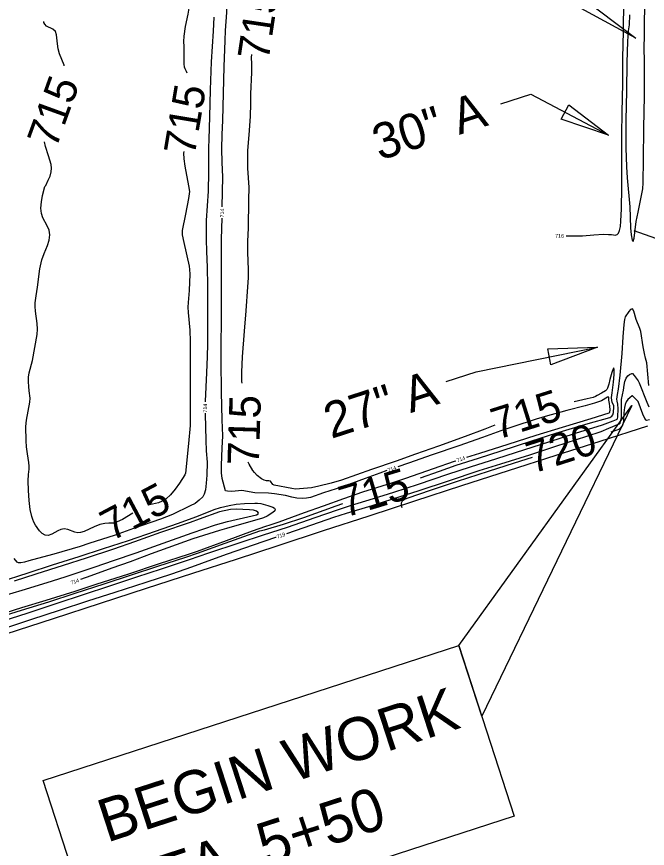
# Model space of a CAD drawing. Extents: x -468563856 to 36492962, y -306094093 to 11899197.
# Drawn here: x 1823721 to 1824382, y 531405 to 532278 of the extents above; entities that cross this region are included whole.
import ezdxf

# ---------------------------------------------------------------- set-up
doc = ezdxf.new("R2010")
doc.units = 0
for name, color, linetype in [('DT_X_Contour_Minor', 7, 'Continuous'), ('Level 14', 7, 'Continuous'), ('Level 19', 7, 'Continuous'), ('Level 40', 7, 'Continuous'), ('SH_Text', 7, 'Continuous')]:
    doc.layers.add(name, color=color, linetype=linetype)

msp = doc.modelspace()

# ---------------------------------------------------------------- linework, layer by layer
at = {"layer": 'DT_X_Contour_Minor'}
for points in [[(1823936.35, 532078.45), (1823936.84, 532109.8), (1823936.37, 532124.67), (1823935.82, 532139.18), (1823936.31, 532154.27), (1823936.92, 532168.73), (1823937.48, 532197.51), (1823938.25, 532225.05), (1823939.35, 532252.79), (1823939.74, 532263.35), (1823941.09, 532282.1), (1823941.07, 532286.43), (1823940.19, 532299.37), (1823939.03, 532314.28), (1823939, 532322.4), (1823939.58, 532333.47), (1823939.57, 532335.1)], [(1823900.62, 532322.38), (1823902.49, 532304.97), (1823902.74, 532297.16), (1823901.79, 532288.98), (1823900.27, 532280.33), (1823897.5, 532267.5), (1823895.93, 532257.35), (1823895.65, 532251.73), (1823895.98, 532246.56), (1823896.09, 532228.14), (1823896.49, 532225.16), (1823897.07, 532223.46), (1823898.5, 532220.8), (1823899.3, 532218.83)], [(1824296.77, 532047.81), (1824313.98, 532048.01), (1824326.04, 532048.84), (1824335.94, 532049.65), (1824341.47, 532049.4), (1824344.46, 532049.14), (1824346.56, 532049.13), (1824348.3, 532048.76), (1824349.31, 532048.82), (1824350.53, 532049.37), (1824351.81, 532050.79), (1824352.95, 532053.49), (1824353.8, 532057.73), (1824354.37, 532063.21), (1824354.99, 532076.15), (1824355.22, 532098.93), (1824355.27, 532129.3), (1824355.26, 532153.68), (1824355.59, 532177.75), (1824356.27, 532207.58), (1824356.51, 532234.37), (1824356.94, 532262.76), (1824357.52, 532294.42)], [(1824363.4, 532279.71), (1824362.83, 532269.19), (1824361.89, 532263.08), (1824361.18, 532251.83), (1824360.5, 532229.71), (1824360.19, 532200.16), (1824359.61, 532168.94), (1824359.6, 532140.1), (1824360.05, 532120.3), (1824360.82, 532108.7), (1824363.65, 532078.16), (1824364.37, 532056.36), (1824365.13, 532048.96), (1824366.14, 532043.44), (1824367.17, 532041.8), (1824368.08, 532045.41), (1824370.43, 532062.77), (1824372.28, 532072.86), (1824377.4, 532097.37), (1824377.78, 532103.67), (1824378.03, 532128.04), (1824378.24, 532160.96), (1824379.06, 532194.65), (1824379.18, 532218.7), (1824379.03, 532236.19), (1824378.85, 532239.97), (1824378.92, 532263.33), (1824379.43, 532296.21)], [(1823770.76, 532226.24), (1823770.62, 532226.78), (1823765.81, 532238.79), (1823764.36, 532244.05), (1823763.43, 532249.41), (1823762.66, 532258.77), (1823761.34, 532262.23), (1823758.6, 532264.66), (1823752.13, 532268), (1823750.26, 532269.76), (1823749.37, 532271.53), (1823749.13, 532272.88)], [(1823927.36, 532277.28), (1823926.67, 532262.57), (1823924.85, 532230.5), (1823923.7, 532201.14), (1823922.98, 532172.63), (1823922.35, 532149.37), (1823921.91, 532140.19), (1823921.98, 532114.75), (1823921.47, 532094.64), (1823919.63, 532063.92), (1823919.36, 532044.19), (1823919.96, 532031.4), (1823920.68, 532015.11), (1823920.99, 531995.3), (1823920.79, 531965.16), (1823920.76, 531934.35), (1823920.61, 531921.2), (1823919.81, 531904.04), (1823918.41, 531874.62), (1823918.41, 531873.76)], [(1823957.11, 531893.22), (1823956.91, 531895.16), (1823956.87, 531904.8), (1823957.7, 531921.1), (1823959.64, 531947.83), (1823961.58, 531969.23), (1823963.12, 531994.35), (1823964.02, 532003.83), (1823963.93, 532012.68), (1823963.01, 532030.56), (1823963.1, 532042.41), (1823963.83, 532056.08), (1823964.31, 532085.69), (1823964.48, 532098.76), (1823963.31, 532118.91), (1823963.27, 532137.51), (1823963.7, 532145.5), (1823965.03, 532158.44), (1823965.95, 532173.45), (1823966.26, 532186.26), (1823966.37, 532196.82), (1823967.43, 532219.13), (1823967.22, 532228.32), (1823967.09, 532235.12), (1823967.26, 532237.99)], [(1823842.53, 531757.04), (1823831.85, 531750.48), (1823823.12, 531746.45), (1823817.59, 531746.52), (1823813.21, 531746.14), (1823807.94, 531744.96), (1823802.18, 531742.75), (1823791.61, 531737.86), (1823787.88, 531736.64), (1823784.84, 531736.47), (1823781.79, 531737.18), (1823774.31, 531739.89), (1823770.54, 531740.56), (1823767.2, 531740), (1823764.1, 531738.53), (1823757.52, 531734.85), (1823753.98, 531733.72), (1823750.57, 531733.83), (1823747.51, 531735.52), (1823744.83, 531738.32), (1823740.57, 531744.52), (1823738.96, 531747.41), (1823737.65, 531750.34), (1823736.63, 531753.48), (1823735.11, 531760.86), (1823733.94, 531770.17), (1823733.12, 531780.89), (1823732.86, 531790.82), (1823733.31, 531797.51), (1823733.78, 531803.14), (1823733.78, 531806.39), (1823733.51, 531810.2), (1823732.2, 531819.21), (1823731.06, 531826.43), (1823730.63, 531832.89), (1823730.5, 531847.78), (1823731.02, 531854.6), (1823734.67, 531873.36), (1823734.86, 531877.59), (1823734.04, 531885.24), (1823733.47, 531889.72), (1823733.12, 531894.61), (1823733.26, 531899.54), (1823734.04, 531904.23), (1823737.36, 531917.04), (1823742.38, 531944.37), (1823742.74, 531950.08), (1823742.16, 531955.9), (1823740.42, 531969.05), (1823740.13, 531973.64), (1823740.27, 531977.53), (1823741.4, 531984.94), (1823742.76, 531994.12), (1823745, 532013.22), (1823747.25, 532022.89), (1823749.45, 532029.42), (1823752.97, 532037.79), (1823754.77, 532043.33), (1823755.56, 532048.86), (1823754.75, 532053.81), (1823752.8, 532058.25), (1823748.26, 532066.7), (1823746.72, 532071.4), (1823746.14, 532076.99), (1823746.67, 532083.61), (1823747.86, 532090.21), (1823750.17, 532099.52), (1823751.23, 532100.72), (1823753.96, 532106.21), (1823755.74, 532110.63), (1823757.06, 532115.08), (1823757.45, 532118.93), (1823756.98, 532122.58), (1823754.2, 532131.75), (1823751.01, 532141.73), (1823749.93, 532146.48)], [(1823895.95, 532136.49), (1823895.71, 532134.58), (1823895.99, 532128.66), (1823897.07, 532120.83), (1823900.94, 532100.27), (1823901.95, 532094.45), (1823901.79, 532091.89), (1823901.07, 532087.11), (1823897.87, 532070.58), (1823894.36, 532053.67), (1823894.15, 532051.26), (1823894.34, 532048.91), (1823896.04, 532040.98), (1823901.68, 532016.18), (1823902.12, 532012.64), (1823902.18, 532007.61), (1823901.55, 531990.54), (1823900.7, 531977.85), (1823900.09, 531973.08), (1823900.49, 531967.48), (1823902.27, 531948.94), (1823902.8, 531937.11), (1823902.77, 531918.95), (1823902.6, 531885.94), (1823902.63, 531853.43), (1823902.57, 531848.94), (1823900.83, 531829.95), (1823897.89, 531799.03), (1823897.02, 531797.32), (1823891.43, 531788.56), (1823886.89, 531782.2), (1823882.11, 531776.33), (1823877.67, 531772.11), (1823873.5, 531769.43), (1823869.33, 531767.86), (1823860.15, 531765.9), (1823858.51, 531765.34)], [(1824109.08, 531801.63), (1824101.49, 531799), (1824086.27, 531793.49), (1824062.27, 531784.52), (1824042.53, 531778.19), (1824028.73, 531773.58), (1824024.55, 531772.57), (1824020.45, 531772.43), (1824014.43, 531772.68), (1824009.23, 531773.79), (1824002.52, 531775.37), (1823991.15, 531777.26), (1823984.89, 531777.81), (1823970.52, 531778.46), (1823956.86, 531780.65), (1823946.38, 531779.76), (1823941.95, 531780.12), (1823939.65, 531780.58), (1823936.39, 531793.47), (1823935.82, 531796.36), (1823935.54, 531799.1), (1823935.58, 531807.46), (1823936.38, 531825.25), (1823936.9, 531838.23), (1823936.24, 531855.03), (1823935.45, 531883.75), (1823935.04, 531916.68), (1823935.14, 531933.74), (1823935.55, 531958.58), (1823935.65, 531991.41), (1823935.42, 532021.22), (1823935.62, 532044.42), (1823936.1, 532066.45)], [(1824383.57, 531891), (1824381.43, 531914.77), (1824380.29, 531919.45), (1824378.92, 531924.51), (1824377.62, 531931.53), (1824375.16, 531947.4), (1824374.25, 531950.68), (1824370.41, 531960.26), (1824367.85, 531968.95), (1824366.33, 531971.29), (1824364.51, 531970.77), (1824362.6, 531968.47), (1824358.74, 531963.02), (1824358.01, 531960.14), (1824357.34, 531954.92), (1824356.32, 531942.06), (1824355.24, 531924.38), (1824353.11, 531901.79), (1824351.55, 531887.2), (1824350.55, 531881.53), (1824349.61, 531876.44), (1824350.02, 531874.52), (1824350.72, 531871.47), (1824351, 531866.36), (1824350.75, 531858.08), (1824350.31, 531856.01), (1824349.91, 531855.34), (1824349.28, 531854.83), (1824346.04, 531853.47), (1824334.56, 531849.28), (1824306.53, 531840.69), (1824278.26, 531831.62), (1824253.23, 531823.42), (1824224.03, 531814.11), (1824196.14, 531805.42), (1824172.51, 531797.63), (1824141.77, 531787.05), (1824116.03, 531778.69), (1824094.41, 531772.1)], [(1824144.21, 531793.99), (1824164.06, 531801.15), (1824181.65, 531807.42), (1824205.01, 531814.8), (1824228.79, 531822.36), (1824260.88, 531832.71), (1824286.24, 531840.79), (1824319.87, 531851.19), (1824342.61, 531857.47), (1824344.86, 531858.63), (1824345.99, 531860.24), (1824346.6, 531862.6), (1824347.06, 531868.64), (1824346.91, 531869.67), (1824345.25, 531873.3), (1824344.71, 531875.11), (1824344.5, 531878.46), (1824345.24, 531883.28), (1824346.72, 531894.54), (1824347.28, 531902.47), (1824347.41, 531907.08), (1824347.06, 531909.49), (1824346.05, 531908.26), (1824344.71, 531904.62), (1824342.76, 531897.35), (1824341.77, 531892.24), (1824340.31, 531888.28), (1824339.51, 531886.88), (1824338.18, 531885.49), (1824333.97, 531882.93), (1824329.62, 531880.44), (1824327.79, 531879.29), (1824325.29, 531878.44), (1824319.1, 531876.92), (1824305.2, 531873.89)], [(1824004.16, 531735.72), (1824022.15, 531741.83), (1824053.45, 531752.83), (1824066.75, 531757.03), (1824093.4, 531764.94), (1824115.3, 531771.93), (1824142.71, 531780.82), (1824173.62, 531791.06), (1824205.68, 531801.62), (1824228.36, 531808.66), (1824258.77, 531818.28), (1824286.03, 531827.24), (1824318.77, 531837.89), (1824333.6, 531842.75), (1824341.79, 531846.05), (1824352.62, 531850.84), (1824353.51, 531851.45), (1824354.03, 531853.01), (1824354.67, 531855.69), (1824354.89, 531857.53), (1824354.84, 531876.39), (1824357.12, 531885.88), (1824357.75, 531891.21), (1824358.47, 531895.04), (1824359.68, 531898.53), (1824361.44, 531900.95), (1824363.36, 531902.41), (1824365.9, 531903.57), (1824366.47, 531903.45), (1824368.14, 531901.37), (1824372.56, 531895.66), (1824373.5, 531893.78), (1824381.59, 531873.57), (1824383.77, 531868.62)], [(1824384.33, 531854.89), (1824381.16, 531854.1), (1824380.76, 531854.5), (1824379.57, 531856.27), (1824377.42, 531860.7), (1824372.4, 531874.11), (1824371.87, 531874.87), (1824366.65, 531880.14), (1824366.08, 531880.11), (1824363.57, 531878.12), (1824361.66, 531876.21), (1824359.93, 531873.79), (1824358.75, 531870.93), (1824358.08, 531867.9), (1824357.58, 531862.4), (1824357.18, 531854.18), (1824356.78, 531851.4), (1824355.92, 531849.23), (1824354.16, 531846.69), (1824352.5, 531844.96), (1824351.13, 531844.34), (1824343.84, 531841.97)], [(1824192.82, 531815.72), (1824206.59, 531820.11), (1824236.14, 531829.34), (1824265.38, 531838.65), (1824293.16, 531847.38), (1824323.17, 531856.44), (1824342.1, 531862.08), (1824342.63, 531862.83), (1824343.04, 531865.22), (1824342.9, 531869.3), (1824342.51, 531872.05), (1824341.71, 531875.66), (1824341.6, 531878.21), (1824341.15, 531878.88), (1824340.17, 531878.63), (1824333.9, 531874.75), (1824326.76, 531872.28), (1824316.92, 531869.43), (1824297.69, 531864.52), (1824274.84, 531858.32), (1824265.41, 531855.59), (1824241.18, 531847.69), (1824228.43, 531843.25), (1824209.29, 531836.28), (1824184.38, 531827.6), (1824156.29, 531818.14), (1824131.64, 531809.44), (1824120.42, 531805.55)], [(1823918.39, 531861.76), (1823918.39, 531861.02), (1823918.97, 531833.61), (1823919.63, 531822.23), (1823920.41, 531810.49), (1823920.12, 531796.86), (1823919.56, 531788.49), (1823918.71, 531781.35), (1823917.53, 531776.77), (1823916.05, 531774.15), (1823912.29, 531770.69), (1823907.78, 531767.31), (1823902.55, 531764.54), (1823884.35, 531755.73), (1823871.57, 531750.76), (1823843.31, 531740.94), (1823824.01, 531734.05), (1823796.49, 531725.12), (1823787.34, 531722.17), (1823759.61, 531714.11), (1823748.01, 531710.84), (1823733.7, 531706.98), (1823729.05, 531705.68), (1823725.28, 531704.92), (1823722.84, 531705.01), (1823721.45, 531705.71), (1823718.09, 531709.48)], [(1824222.24, 531849.26), (1824211.52, 531845.09), (1824190.96, 531837.3), (1824163.17, 531827.33), (1824139.13, 531818.76), (1824118.77, 531811.58), (1824092.95, 531802.93), (1824061.44, 531791.78), (1824050.55, 531788.64), (1824037.49, 531785.32), (1824029.81, 531783.52), (1824013.08, 531782.27), (1824009.3, 531782.78), (1823990.77, 531786.37), (1823989.29, 531787.2), (1823987, 531790.61), (1823985.23, 531790.92), (1823982.82, 531791.04), (1823980.12, 531791.57), (1823977.47, 531792.92), (1823973, 531796.58), (1823969.99, 531799.58), (1823968.47, 531801.65), (1823964.61, 531808.41), (1823963.65, 531810.48)], [(1823700.56, 531650.16), (1823726.33, 531658.02), (1823751.56, 531665.77), (1823782.04, 531675.33), (1823805.32, 531682.79), (1823837.25, 531693.19), (1823870.41, 531704.04), (1823901.05, 531713.88), (1823910.47, 531717.22), (1823940.7, 531728.44), (1823967.89, 531738.4), (1823981.96, 531743.35), (1823986.49, 531744.59), (1823996.18, 531747.81), (1824022.51, 531757.74), (1824042.6, 531764.82), (1824063.85, 531772.23), (1824083.9, 531779.24), (1824114.22, 531788.82), (1824128.72, 531793.65), (1824157.71, 531804.02), (1824180, 531811.62), (1824181.39, 531812.07)], [(1824261.32, 531815.5), (1824242.29, 531809.42), (1824215.26, 531800.74), (1824182.61, 531790.17), (1824154.38, 531780.78), (1824130.76, 531772.88), (1824127.51, 531771.45), (1824124.97, 531769.64), (1824123.91, 531767.55), (1824123.97, 531765.39), (1824124.54, 531763.11)], [(1823583.08, 531610.8), (1823594.37, 531614.4), (1823623.25, 531623.96), (1823652.75, 531633.25), (1823672.99, 531639.28), (1823702.13, 531647.92), (1823725.93, 531655.23), (1823754.43, 531664.04), (1823782.25, 531673.11), (1823812.54, 531682.93), (1823841.29, 531692.45), (1823868.78, 531701.42), (1823898.18, 531710.9), (1823910.33, 531715.09), (1823939.28, 531725.57), (1823959.03, 531732.51), (1823975.7, 531738.36), (1823980.58, 531739.43), (1824000.39, 531745.51), (1824021.94, 531752.61), (1824055.92, 531764.58), (1824062.87, 531767.11)], [(1823702.23, 531684.46), (1823732.69, 531694.25), (1823758.41, 531702.67), (1823786.4, 531711.63), (1823811.85, 531719.85), (1823838.04, 531728.37), (1823866.29, 531738), (1823889.46, 531746.08), (1823909.71, 531753.65), (1823927.84, 531760.74), (1823934.54, 531762.83), (1823943.72, 531764.98), (1823951.02, 531766.36), (1823959.83, 531766.99), (1823970.59, 531767.59), (1823973.41, 531767.46), (1823976.67, 531766.98), (1823984.15, 531765), (1823989.55, 531763.22), (1823991.23, 531762.1), (1823991.94, 531761.01), (1823991.53, 531759.49), (1823989.47, 531757.6), (1823983.43, 531753.9), (1823979.72, 531752.04), (1823977.51, 531751.37), (1823971.12, 531749.68), (1823940.83, 531741.01), (1823933.35, 531738.8), (1823905.65, 531730.24), (1823888.07, 531723.92), (1823861.84, 531714.29), (1823839.72, 531706.02), (1823820.7, 531699.19), (1823798.66, 531691.29), (1823787.88, 531687.47)], [(1824094.41, 531772.1), (1824070.46, 531764.85), (1824056.89, 531760.22), (1824033.57, 531751.98), (1824004.52, 531742.03), (1823979.14, 531733.88), (1823953.67, 531725.47), (1823922.02, 531714.99), (1823901.65, 531708.01), (1823872.24, 531698.36), (1823846.27, 531689.91), (1823817.97, 531680.59), (1823790.62, 531671.42), (1823762.73, 531662.08), (1823732.63, 531651.98), (1823705.27, 531643.44)], [(1823707.77, 531670.66), (1823726.66, 531676.16), (1823752.83, 531684.15), (1823771.8, 531690.17), (1823803.05, 531700.88), (1823822.39, 531707.36), (1823846.25, 531715.24), (1823874.45, 531725.45), (1823904.74, 531736.37), (1823929.2, 531744.75), (1823941.76, 531748.37), (1823967.62, 531754.13), (1823972.29, 531755.29), (1823973.89, 531756.13), (1823974.48, 531757.07), (1823973.82, 531758.05), (1823972.33, 531758.95), (1823969.09, 531760.07), (1823965.04, 531760.47), (1823950.84, 531761.15), (1823944.93, 531760.87), (1823933.41, 531758.42), (1823912.07, 531750.62), (1823902.55, 531747.26), (1823871.63, 531736.56), (1823844.45, 531726.97), (1823822.21, 531719.28), (1823793.58, 531709.7), (1823769.63, 531701.97), (1823741.04, 531692.87), (1823718.08, 531685.81)], [(1823683.11, 531628.14), (1823709.45, 531636.8), (1823736.68, 531645.7), (1823765.62, 531655.27), (1823795.33, 531664.93), (1823824.19, 531674.26), (1823856.47, 531684.61), (1823883.31, 531693.48), (1823904.53, 531700.65), (1823925.53, 531708.47), (1823941.77, 531714.29), (1823969.1, 531723.78), (1823992.51, 531731.76), (1823992.8, 531731.86)]]:
    msp.add_lwpolyline(points, dxfattribs=at)
at = {"layer": 'Level 14'}
for points in [[(1824382.26, 531848.18), (1824332.09, 531832.12), (1824285.97, 531817.36), (1824236.06, 531801.4), (1824187.06, 531785.59), (1824138.09, 531769.45), (1824090.03, 531753.88), (1824042.3, 531738.32), (1823994.71, 531722.69), (1823950.89, 531708.48), (1823905.32, 531693.73)], [(1823905.32, 531693.73), (1823856.68, 531677.81), (1823808.23, 531662.16), (1823759.17, 531646.3), (1823709.45, 531630.09), (1823663.76, 531615.33), (1823626.69, 531603.28), (1823592.93, 531592.11), (1823546.85, 531577.13), (1823502.6, 531562.57), (1823453.47, 531546.49), (1823404.63, 531530.76), (1823355.72, 531514.87), (1823306.7, 531499.05), (1823260.73, 531484.09), (1823213.94, 531468.77), (1823166.5, 531453.32), (1823118.2, 531437.61), (1823073.63, 531423.06), (1823030.5, 531409.05)]]:
    msp.add_lwpolyline(points, dxfattribs=at)
at = {"layer": 'Level 40'}
for p, q in [((1824228.45, 532186.4), (1824260.07, 532196.66)), ((1824260.07, 532196.66), (1824341.39, 532153.67)), ((1824291.79, 532170.19), (1824299.82, 532185.37)), ((1824299.82, 532185.37), (1824341.39, 532153.67)), ((1824341.39, 532153.67), (1824291.79, 532170.19)), ((1824367.85, 532053.61), (1824793.59, 531898.99)), ((1824202.69, 531905.4), (1824329.85, 531931.08)), ((1824277.59, 531929.3), (1824329.85, 531931.08)), ((1824280.99, 531912.46), (1824277.59, 531929.3)), ((1824329.85, 531931.08), (1824280.99, 531912.46)), ((1824171.07, 531895.14), (1824202.69, 531905.4))]:
    msp.add_line(p, q, dxfattribs=at)
at = {"layer": 'SH_Text'}
for points in [[(1824017.05, 532521.06), (1824369.99, 532255.38), (1824046.09, 532431.61)], [(1824184.36, 531618.11), (1824365.9, 531869.81), (1824208.35, 531544.22)], [(1824242.45, 531439.19), (1823806.68, 531297.71), (1823748.59, 531476.63), (1824184.36, 531618.11)]]:
    msp.add_lwpolyline(points, close=True, dxfattribs=at)

# ---------------------------------------------------------------- texts
at = {"layer": 'Level 19'}
for s, height, rotation, p in [('715', 33, 81.51471, (1823984.84, 532230.87)), ('715', 33, 70.05406, (1823761.99, 532138.39)), ('715', 33, 80.48338, (1823907.3, 532130.95)), ('714', 4, 88.74543, (1823938.12, 532067.2)), ('716', 4, 358.72315, (1824285.37, 532045.99)), ('715', 33, 17.51532, (1824224.55, 531833.87)), ('714', 4, 89.92, (1823920.4, 531862.55)), ('715', 33, 88.26415, (1823974.72, 531806.86)), ('720', 33, 17.79034, (1824261.63, 531798.25)), ('714', 4, 17.71013, (1824182.75, 531810.4)), ('715', 33, 16.82777, (1824064.84, 531752.15)), ('714', 4, 19.09668, (1824110.48, 531799.99)), ('715', 33, 27.89731, (1823819.98, 531726.97)), ('719', 4, 18.76437, (1823994.14, 531730.2)), ('714', 4, 19.52067, (1823777.98, 531681.83))]:
    msp.add_text(s, height=height, rotation=rotation, dxfattribs=at).set_placement(p)
at = {"layer": 'Level 40'}
for s, p in [('30" A', (1824101.4, 532126.69)), ('27" A', (1824050.53, 531834.81))]:
    msp.add_text(s, height=37.5, rotation=17.9864, dxfattribs=at).set_placement(p)
at = {"layer": 'SH_Text'}
for s, p in [('BEGIN WORK', (1823815.34, 531411.25)), ('STA. 5+50', (1823838.54, 531339.8))]:
    msp.add_text(s, height=45.072, rotation=17.9864, dxfattribs=at).set_placement(p)

doc.saveas('drawing.dxf')
